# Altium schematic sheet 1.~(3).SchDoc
size 420 x 297 mm
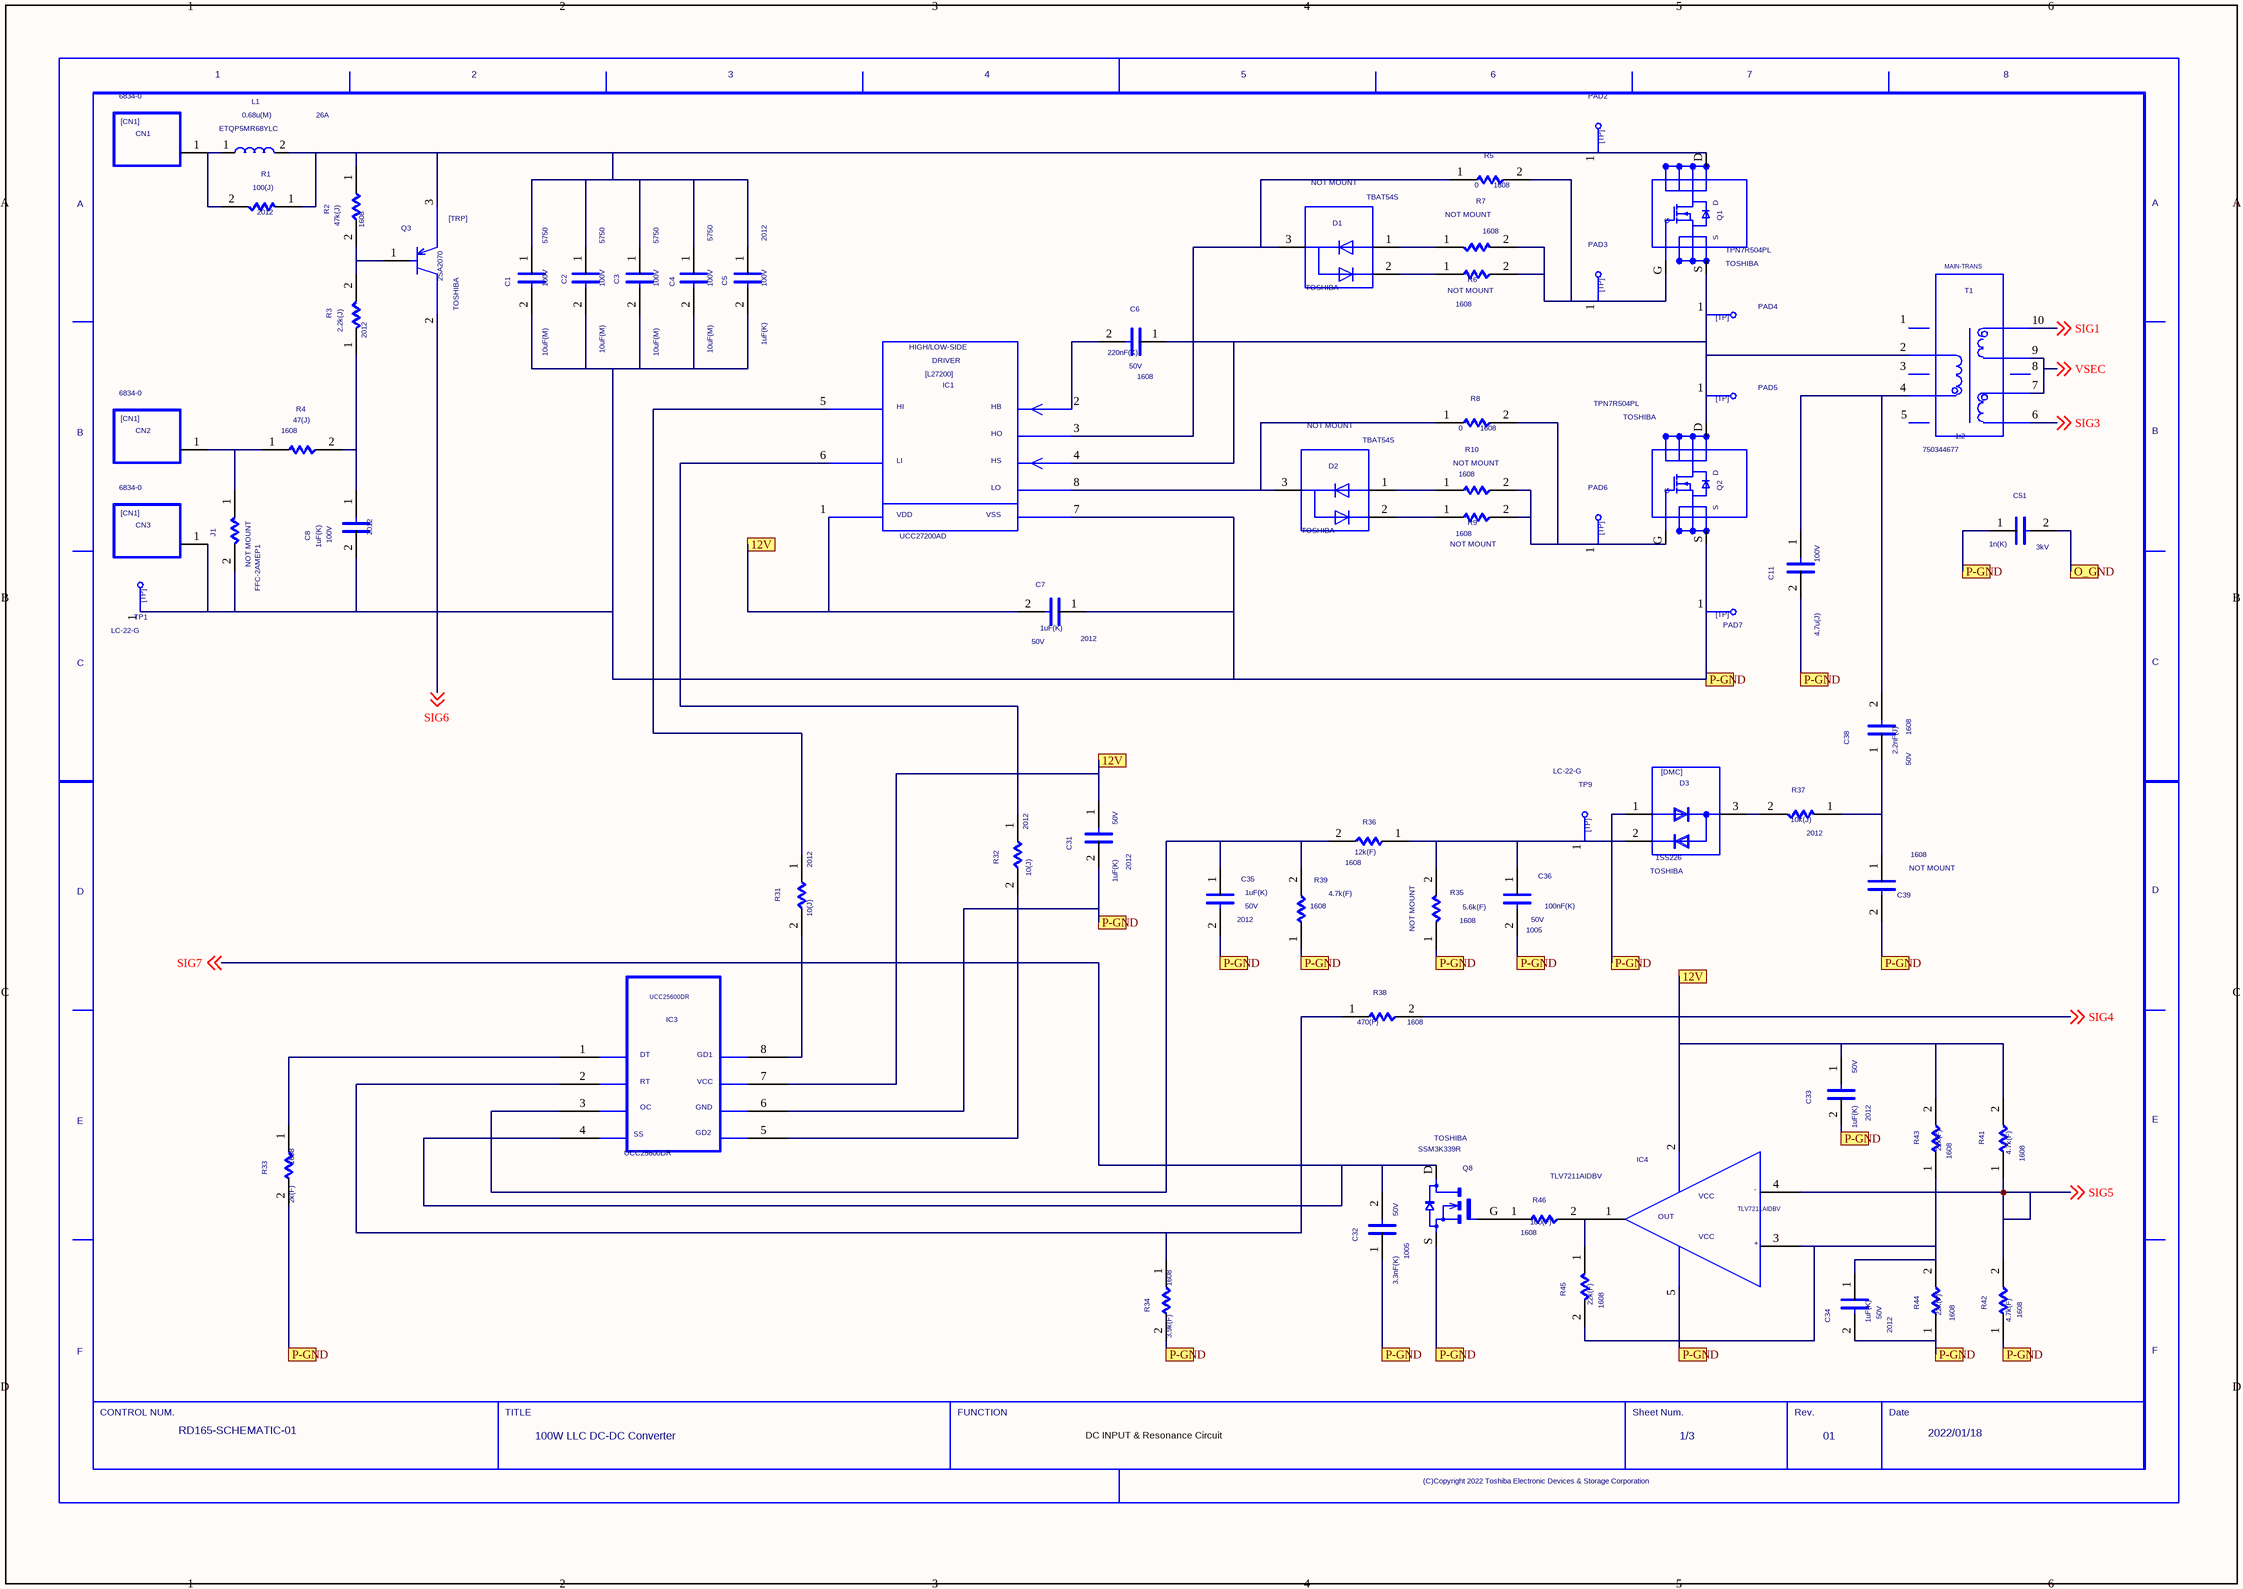
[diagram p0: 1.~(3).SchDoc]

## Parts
C1  SIZECODESMD: 5750  VAL2: 100V  VAL1: 10uF(M)  (hidden comment: C)
C2  SIZECODESMD: 5750  VAL2: 100V  VAL1: 10uF(M)  (hidden comment: C)
C3  SIZECODESMD: 5750  VAL2: 100V  VAL1: 10uF(M)  (hidden comment: C)
C4  SIZECODESMD: 5750  VAL2: 100V  VAL1: 10uF(M)  (hidden comment: C)
C5  SIZECODESMD: 2012  VAL2: 100V  VAL1: 1uF(K)  (hidden comment: C)
C6  SIZECODESMD: 1608  VAL2: 50V  VAL1: 220nF(K)  (hidden comment: C)
C7  SIZECODESMD: 2012  VAL2: 50V  VAL1: 1uF(K)  (hidden comment: C)
C8  SIZECODESMD: 2012  VAL2: 100V  VAL1: 1uF(K)  (hidden comment: C)
C11  VAL2: 100V  VAL1: 4.7u(J)  (hidden comment: C)
C31  SIZECODESMD: 2012  VAL2: 50V  VAL1: 1uF(K)  (hidden comment: C)
C32  SIZECODESMD: 1005  VAL2: 50V  VAL1: 3.3nF(K)  (hidden comment: C)
C33  SIZECODESMD: 2012  VAL2: 50V  VAL1: 1uF(K)  (hidden comment: C)
C34  SIZECODESMD: 2012  VAL2: 50V  VAL1: 1uF(K)  (hidden comment: C)
C35  SIZECODESMD: 2012  VAL2: 50V  VAL1: 1uF(K)  (hidden comment: C)
C36  SIZECODESMD: 1005  VAL2: 50V  VAL1: 100nF(K)  (hidden comment: C)
C38  SIZECODESMD: 1608  VAL2: 50V  VAL1: 2.2nF(J)  (hidden comment: C)
C39  NOTMOUNT: NOT MOUNT  SIZECODESMD: 1608  (hidden comment: C)
C51  VAL2: 3kV  VAL1: 1n(K)  (hidden comment: C)
CN1  VAL3: 6834-0  (hidden comment: CN1)
CN2  VAL3: 6834-0  (hidden comment: CN1)
CN3  VAL3: 6834-0  (hidden comment: CN1)
D1  USERCOMPTEXT3: TOSHIBA  NOTMOUNT: NOT MOUNT  (hidden comment: TBAT54S)
D2  USERCOMPTEXT3: TOSHIBA  NOTMOUNT: NOT MOUNT  (hidden comment: TBAT54S)
D3  USERCOMPTEXT3: TOSHIBA  VAL3: 1SS226  (hidden comment: DMC)
IC1  VAL3: UCC27200AD  (hidden comment: L27200)
IC3  UCC25600DR
IC4  TLV7211AIDBV
J1  VAL3: FFC-2AMEP1  NOTMOUNT: NOT MOUNT  (hidden comment: R)
L1  VAL3: ETQP5MR68YLC  VAL2: 26A  VAL1: 0.68u(M)  (hidden comment: L)
PAD2  TP  (value not drawn)
PAD3  TP  (value not drawn)
PAD4  TP  (value not drawn)
PAD5  TP  (value not drawn)
PAD6  TP  (value not drawn)
PAD7  TP  (value not drawn)
Q1  USERCOMPTEXT3: TOSHIBA  VAL3: TPN7R504PL  (hidden comment: TPN7B504PL)
Q2  USERCOMPTEXT3: TOSHIBA  VAL3: TPN7R504PL  (hidden comment: TPN7B504PL)
Q3  USERCOMPTEXT3: TOSHIBA  VAL3: 2SA2070  (hidden comment: TRP)
Q8  USERCOMPTEXT3: TOSHIBA  VAL3: SSM3K339R  (hidden comment: MFNF)
R1  SIZECODESMD: 2012  VAL1: 100(J)  (hidden comment: R)
R2  SIZECODESMD: 1608  VAL1: 47k(J)  (hidden comment: R)
R3  SIZECODESMD: 2012  VAL1: 2.2k(J)  (hidden comment: R)
R4  SIZECODESMD: 1608  VAL1: 47(J)  (hidden comment: R)
R5  SIZECODESMD: 1608  VAL1: 0  (hidden comment: R)
R6  NOTMOUNT: NOT MOUNT  SIZECODESMD: 1608  (hidden comment: R)
R7  NOTMOUNT: NOT MOUNT  SIZECODESMD: 1608  (hidden comment: R)
R8  SIZECODESMD: 1608  VAL1: 0  (hidden comment: R)
R9  NOTMOUNT: NOT MOUNT  SIZECODESMD: 1608  (hidden comment: R)
R10  NOTMOUNT: NOT MOUNT  SIZECODESMD: 1608  (hidden comment: R)
R31  SIZECODESMD: 2012  VAL1: 10(J)  (hidden comment: R)
R32  SIZECODESMD: 2012  VAL1: 10(J)  (hidden comment: R)
R33  SIZECODESMD: 1608  VAL1: 2k(F)  (hidden comment: R)
R34  SIZECODESMD: 1608  VAL1: 3.9k(F)  (hidden comment: R)
R35  NOTMOUNT: NOT MOUNT  SIZECODESMD: 1608  VAL1: 5.6k(F)  (hidden comment: R)
R36  SIZECODESMD: 1608  VAL1: 12k(F)  (hidden comment: R)
R37  SIZECODESMD: 2012  VAL1: 10k(J)  (hidden comment: R)
R38  SIZECODESMD: 1608  VAL1: 470(F)  (hidden comment: R)
R39  SIZECODESMD: 1608  VAL1: 4.7k(F)  (hidden comment: R)
R41  SIZECODESMD: 1608  VAL1: 4.7k(F)  (hidden comment: R)
R42  SIZECODESMD: 1608  VAL1: 4.7k(F)  (hidden comment: R)
R43  SIZECODESMD: 1608  VAL1: 22k(F)  (hidden comment: R)
R44  SIZECODESMD: 1608  VAL1: 22k(F)  (hidden comment: R)
R45  SIZECODESMD: 1608  VAL1: 22k(F)  (hidden comment: R)
R46  SIZECODESMD: 1608  VAL1: 100(F)  (hidden comment: R)
T1  VAL1: 1:2  VAL3: 750344677  (hidden comment: TRANS)
TP1  VAL3: LC-22-G  (hidden comment: TP)
TP9  VAL3: LC-22-G  (hidden comment: TP)
U?  DATE: 2022/01/18  TITLE: 100W LLC DC-DC Converter  REVISION: 01  SHEETNUMBER: 1/3  DRAWINGNUMBER: RD165-SCHEMATIC-01  (hidden comment: WAKU_DEF100)

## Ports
12V, O_GND, P-GND

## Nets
DN000002: IC3.2 R34.1 R38.1
DN000007: C11.1 C38.2 T1.4
DN000046: IC3.1 R33.1
N04422: C1.1 C2.1 C3.1 C4.1 C5.1 L1.2 PAD2.1 Q1.D Q3.3(E) R1.1 R2.1
N216469: Q3.1(B) R2.2 R3.2
N216829: C8.1 R3.1 R4.2
N216837: CN2.1 J1.1 R4.1
O_GND: C51.2 ; port O_GND
SIG1: T1.10 ; off-sheet SIG1
SIG3: T1.6 ; off-sheet SIG3
SIG4: R38.2 ; off-sheet SIG4
SIG5: IC4.4 R41.1 R42.2 ; off-sheet SIG5
SIG6: Q3.2(C) ; off-sheet SIG6
SIG7: C32.2 IC3.4 Q8.D ; off-sheet SIG7
SIG67: IC3.8 R31.2
SIG85: C34.1 IC4.3 R43.1 R44.2 R45.2
SIG102: C38.1 C39.1 R37.1
SIG104: C7.2 C31.1 C33.1 IC1.1 IC3.7 IC4.2 R41.2 R43.2 ; port 12V  [also labelled SIG130]
SIG119: CN1.1 L1.1 R1.2
SIG125: D2.3 IC1.8 R8.1
SIG126: IC1.6 R32.1
SIG127: IC1.5 R31.1
SIG128: D1.3 IC1.3 R5.1
SIG129: C6.2 IC1.2
SIG131: C6.1 IC1.4 PAD4.1 PAD5.1 Q1.S Q2.D T1.2
SIG190: IC3.5 R32.2
SIG212: D3.3(AC) R37.2
SIG218: PAD3.1 Q1.G R5.2 R6.2 R7.2
SIG231: PAD6.1 Q2.G R8.2 R9.2 R10.2
SIG233: C36.1 D3.2(C) R35.2 R36.1 TP9.1
SIG237: D2.1 R10.1
SIG239: D1.2 R6.1
SIG240: IC4.1 R45.1 R46.2
SIG248: D1.1 R7.1
SIG249: D2.2 R9.1
SIG267: C1.2 C2.2 C3.2 C4.2 C5.2 C7.1 C8.2 C11.2 C31.2 C32.1 C33.2 C34.2 C35.2 C36.2 C39.2 C51.1 CN3.1 D3.1(A) IC1.7 IC3.6 IC4.5 J1.2 PAD7.1 Q2.S Q8.S R33.2 R34.2 R35.1 R39.1 R42.1 R44.1 TP1.1 ; port P-GND  [also labelled SIG268]
SIG269: C35.1 IC3.3 R36.2 R39.2
SIG270: T1.7 T1.9 ; off-sheet VSEC  [also labelled VSEC]
NetQ8_G: Q8.G R46.1

Not connected (* = marked no-connect by the designer): T1 1 3 5 8

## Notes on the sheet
- DC INPUT & Resonance Circuit

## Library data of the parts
C1-C4 = C: OriginalSymbolOrigin: (2540,7620); RATEDVOLTAGE: 50; MAXGCOUNT: 1; TEMPCHARACTERI2: E; OUMEMAKER: KYC 京セラ; QUADMODEL: CON_10U; FNLEADFREETHET1GT2GMCTH1: N_N_N; OUMECLASSIFICATION: セラミックコンデンサ; CDBNAME: Chip5750_TD; NOMINALCAPACITA: 10u; OUMEMAKERKATAMEI: CX55Y5U106M50AT; CAPACITANCETOLE: M; CDMASTERCADCELG: DC848R; ADSMODELNAME: s_CX55Y5U106M50AT
C5 = C: OriginalSymbolOrigin: (2540,7620); RATEDVOLTAGE: 100; MAXGCOUNT: 1; OUMEMAKER: TDK ＴＤＫ; QUADMODEL: CON_1U; FNLEADFREETHET1GT2GMCTH1: 3_2_N; OUMECLASSIFICATION: セラミックコンデンサ; CDBNAME: Chip2012_GS_1; NOMINALCAPACITA: 1u; PMPRODUCTSTYPEG: HEV; OUMEMAKERKATAMEI: CGA4J3X7S2A105KT@@; CAPACITANCETOLE: K; CDMASTERCADCELG: KC0136; ADSMODELNAME: s_CGA4J3X7S2A105KT@@
C6 = C: OriginalSymbolOrigin: (2540,7620); RATEDVOLTAGE: 50; MAXGCOUNT: 1; OUMEMAKER: TDK ＴＤＫ; QUADMODEL: CON_220N; FNLEADFREETHET1GT2GMCTH1: N_N_N; OUMECLASSIFICATION: セラミックコンデンサ; CDBNAME: Chip1608_GS_1; NOMINALCAPACITA: 220n; PMPRODUCTSTYPEG: DA; OUMEMAKERKATAMEI: CGA3E3X7R1H224KT@@; CAPACITANCETOLE: K; CDMASTERCADCELG: KCK0238; ADSMODELNAME: s_CGA3E3X7R1H224KT@@
C7 C34 = C: OriginalSymbolOrigin: (2540,7620); RATEDVOLTAGE: 50; MAXGCOUNT: 1; OUMEMAKER: TDK ＴＤＫ; QUADMODEL: CON_1U; FNLEADFREETHET1GT2GMCTH1: 3_2_N; OUMECLASSIFICATION: セラミックコンデンサ; CDBNAME: Chip2012_GS_1; NOMINALCAPACITA: 1u; PMPRODUCTSTYPEG: DA; OUMEMAKERKATAMEI: CGA4J3X7R1H105KT@@; CAPACITANCETOLE: K; CDMASTERCADCELG: KC0159; ADSMODELNAME: s_CGA4J3X7R1H105KT@@
C8 C31 = C#1: OriginalSymbolOrigin: (2540,7620); CaptureCellPackProp: C##1; RATEDVOLTAGE: 50; MAXGCOUNT: 1; OUMEMAKER: TDK ＴＤＫ; QUADMODEL: CON_1U; FNLEADFREETHET1GT2GMCTH1: 3_2_N; OUMECLASSIFICATION: セラミックコンデンサ; CDBNAME: Chip2012_GS_1; NOMINALCAPACITA: 1u; PMPRODUCTSTYPEG: DA; OUMEMAKERKATAMEI: CGA4J3X7R1H105KT@@; CAPACITANCETOLE: K; CDMASTERCADCELG: KC0159; ADSMODELNAME: s_CGA4J3X7R1H105KT@@
C11 = C#1: OriginalSymbolOrigin: (2540,7620); CaptureCellPackProp: C##1; CDBNAME: CB182E0475***_AV
C32 = C: OriginalSymbolOrigin: (2540,7620); RATEDVOLTAGE: 50; MAXGCOUNT: 1; OUMEMAKER: TDK ＴＤＫ; QUADMODEL: CON_10N; FNLEADFREETHET1GT2GMCTH1: 3_0_N; OUMECLASSIFICATION: セラミックコンデンサ; CDBNAME: Chip1005_GS_2; NOMINALCAPACITA: 10n; PMPRODUCTSTYPEG: DA; OUMEMAKERKATAMEI: CGA2B3X7R1H103KT@@; CAPACITANCETOLE: K; CDMASTERCADCELG: KC0154; ADSMODELNAME: s_CGA2B3X7R1H103KT@@
C33 = C#1: OriginalSymbolOrigin: (2540,7620); CaptureCellPackProp: C##1; RATEDVOLTAGE: 50; MAXGCOUNT: 1; OUMEMAKER: TDK ＴＤＫ; QUADMODEL: CON_1U; FNLEADFREETHET1GT2GMCTH1: 3_2_N; OUMECLASSIFICATION: セラミックコンデンサ; CDBNAME: Chip2012_GS_1; NOMINALCAPACITA: 1u; PMPRODUCTSTYPEG: DA; OUMEMAKERKATAMEI: CGA4J3X7R1H105KTXXXS@@; CAPACITANCETOLE: K; CDMASTERCADCELG: KC0187; ADSMODELNAME: s_CGA4J3X7R1H105KTXXXS@@
C35 = C: OriginalSymbolOrigin: (2540,7620); CDBNAME: Chip2012_GS_1
C36 = C: OriginalSymbolOrigin: (2540,7620); CDBNAME: Chip1005_GS_2
C38 = C: OriginalSymbolOrigin: (2540,7620); RATEDVOLTAGE: 50; MAXGCOUNT: 1; OUMEMAKER: MRT 村田製作所; QUADMODEL: CON_2.2N; FNLEADFREETHET1GT2GMCTH1: 3_2_N; OUMECLASSIFICATION: セラミックコンデンサ; CDBNAME: Chip1608_GS_1; NOMINALCAPACITA: 2.2n; PMPRODUCTSTYPEG: HEV; OUMEMAKERKATAMEI: GCM1885C1H222JA16D@@; CAPACITANCETOLE: J; CDMASTERCADCELG: KC0134; ADSMODELNAME: s_GCM1885C1H222JA16D@@
C39 = C: OriginalSymbolOrigin: (2540,7620); RATEDVOLTAGE: 50; MAXGCOUNT: 1; OUMEMAKER: TDK ＴＤＫ; QUADMODEL: CON_10N; FNLEADFREETHET1GT2GMCTH1: 3_2_N; OUMECLASSIFICATION: セラミックコンデンサ; CDBNAME: Chip1608_GS_1; NOMINALCAPACITA: 10n; PMPRODUCTSTYPEG: HEV; OUMEMAKERKATAMEI: CGA3E2C0G1H103JT@@; VAL2: 50V; VAL1: 10nF(J); CAPACITANCETOLE: J; CDMASTERCADCELG: KC0134; ADSMODELNAME: s_CGA3E2C0G1H103JT@@
C51 = C: OriginalSymbolOrigin: (2540,7620); CDBNAME: Chip4632_AV
CN1-CN3 = CN1: OUMEPARTTYPE: CN; OriginalSymbolOrigin: (2540,12700); RATEDVOLTAGE: 0; MAXGCOUNT: 1; PLUGDIAMETER: 6m; OUMEMAKER: SMK エスエャPイ; FNLEADFREETHET1GT2GMCTH1: 9_1_N; OUMECLASSIFICATION: 単頭プラグ; CDBNAME: 6834-0-00-**-00-00-03-0_ML; OUMEMAKERKATAMEI: CMI1501-0101; CDMASTERCADCELG: CU0059
D1 D2 = TBAT54S: SAVEAREA0: -9930,-5308,32601,25918; TIME: 14:49:55; UPDATEUSER: t5459927; UPDATETIME: 18:16:07; SAVECOUNT: 5; OriginalSymbolOrigin: (5080,17780); CDBNAME: TBAT54S_TS
D3 = DMC: OUMEPARTTYPE: D; OriginalSymbolOrigin: (5080,20320); FORWARDVOLTAGEM: 0; MAXREVERSEVOLTA: 70; MAXGCOUNT: 1; OUMEMAKER: TSB 東芝; MOUNTINGFORMSMD: SMD; FNLEADFREETHET1GT2GMCTH1: 2_0_N; OUMECLASSIFICATION: 小信号ダイオード; CDBNAME: 1SS226_TS; PMPRODUCTSTYPEG: PC1; OUMEMAKERKATAMEI: 1SS226(TE85R); CDMASTERCADCELG: DD902A; ADSMODELNAME: s_1SS226_TE85R_
IC1 = L27200: OUMEPARTTYPE: IC; SAVEAREA0: -11719,-442,57445,43603; SAVECOUNT: 88; TIME: 14:04:55; UPDATEUSER: 19910145; UPDATETIME: 08:40:41; OriginalSymbolOrigin: (0,40640); MAXGCOUNT: 1; OUMEMAKER: TII テキサスインスツルメンツ; MOUNTINGFORMSMD: SMD; FNLEADFREETHET1GT2GMCTH1: N_N_N; OUMECLASSIFICATION: その他; CDBNAME: UCC272**AD_TI; OUMEMAKERKATAMEI: UCC27200D; CDMASTERCADCELG: I810D8; KIND: OTHER
IC3 = UCC25600DR: SAVEAREA0: -5309,-792,48736,38830; TIME: 17:00:15; UPDATEUSER: t5459927; UPDATETIME: 08:35:41; SAVECOUNT: 3; OriginalSymbolOrigin: (7620,35560); CDBNAME: UCC25600D*_TI
IC4 = TLV7211AIDBV: SAVECOUNT: 19; SAVEAREA0: -11523,-10867,52370,35975; TIME: 20:02:00; UPDATEUSER: t5459927; UPDATETIME: 08:40:37; OriginalSymbolOrigin: (7620,25400); CDBNAME: TLV7211AIDBVR_TI
J1 = R: OriginalSymbolOrigin: (5080,5080); CDBNAME: FFC-2AMEP1_HN
L1 = L: OriginalSymbolOrigin: (2540,5080); CDBNAME: ETQP5M***YLC_PN
PAD2-PAD7 = TP: TIME: 16:12:21; UPDATEUSER: fukuda-y; UPDATETIME: 16:18:11; SAVECOUNT: 2; SAVEAREA0: -242,-92,12810,7836; OriginalSymbolOrigin: (0,7620); CDBNAME: TP_I_TH0.5_LC1.1_RC1.2_GS
Q1 Q2 = TPN7B504PL: SAVEAREA0: -19342,-136,26697,27151; TIME: 18:57:44; UPDATEUSER: t5459927; UPDATETIME: 14:39:22; SAVECOUNT: 22; OriginalSymbolOrigin: (2540,20320); CDBNAME: TPN7R504PL_TS_A
Q3 = TRP: OUMEPARTTYPE: Q; TIME: 09:39:04; UPDATEUSER: 19870035; UPDATETIME: 15:34:42; SAVECOUNT: 12; SAVEAREA0: -5466,-244,29263,20886; OriginalSymbolOrigin: (5080,22860); MAXGCOUNT: 1; OUMEMAKER: TSB 東芝; MOUNTINGFORMSMD: SMD; FNLEADFREETHET1GT2GMCTH1: N_N_N; OUMECLASSIFICATION: PNPバイポーラトランジスタ; CDBNAME: 2SA2070_TS; PMPRODUCTSTYPEG: HD1; MAXGDVOLTAGE: 0; OUMEMAKERKATAMEI: 2SA2070(TE12L,F); CDMASTERCADCELG: DQ901D; ADSMODELNAME: s_2SA2070_TE12L_F_; MAXCOLLECTORCUR: -1
Q8 = MFNF: SAVECOUNT: 13; SAVEAREA0: -36202,-24391,51351,39797; TIME: 17:06:19; UPDATEUSER: t5459927; UPDATETIME: 17:07:36; OriginalSymbolOrigin: (5080,12700); CDBNAME: SSM3K339R_TS_A
R1 = R: OriginalSymbolOrigin: (5080,5080); MAXGCOUNT: 1; OUMEMAKER: NAE パナソニックエレクトロニックデバイス; QUADMODEL: RES_100; MOUNTINGFORMSMD: SMD; FNLEADFREETHET1GT2GMCTH1: 2_2_N; OUMECLASSIFICATION: 表面実装用固定抵抗器; CDBNAME: Chip2012_GS_1; RESISTANCETOLER: J; PMPRODUCTSTYPEG: PC1-PCS; POWERRATING: 250m; OUMEMAKERKATAMEI: ERJP06J101V; NOMINALRESISTAN: 100; VAL2: 400mW; CDMASTERCADCELG: KC0006; ADSMODELNAME: s_ERJP06J101V
R2 = R: OriginalSymbolOrigin: (5080,5080); MAXGCOUNT: 1; OUMEMAKER: NAE パナソニックエレクトロニックデバイス; QUADMODEL: RES_47K; MOUNTINGFORMSMD: SMD; FNLEADFREETHET1GT2GMCTH1: 3_2_N; OUMECLASSIFICATION: 表面実装用固定抵抗器; CDBNAME: Chip1608_GS_1; RESISTANCETOLER: J; PMPRODUCTSTYPEG: HEV; POWERRATING: 100m; OUMEMAKERKATAMEI: ERJ3GEYJ473V@@; NOMINALRESISTAN: 47K; VAL2: 100mW; CDMASTERCADCELG: KC0133; ADSMODELNAME: s_ERJ3GEYJ473V@@
R3 = R: OriginalSymbolOrigin: (5080,5080); MAXGCOUNT: 1; OUMEMAKER: KOA コーア; QUADMODEL: RES_2.2K; MOUNTINGFORMSMD: SMD; FNLEADFREETHET1GT2GMCTH1: 3_1_N; OUMECLASSIFICATION: 表面実装用固定抵抗器; CDBNAME: Chip2012_GS_1; RESISTANCETOLER: J; PMPRODUCTSTYPEG: HEV; POWERRATING: 250m; OUMEMAKERKATAMEI: SG73P2ATTD222J@@; NOMINALRESISTAN: 2.2K; VAL2: 400mW; CDMASTERCADCELG: KC0135; ADSMODELNAME: s_SG73P2ATTD222J@@
R4 = R: OriginalSymbolOrigin: (5080,5080); MAXGCOUNT: 1; OUMEMAKER: KOA コーア; QUADMODEL: RES_47; MOUNTINGFORMSMD: SMD; FNLEADFREETHET1GT2GMCTH1: 3_1_N; OUMECLASSIFICATION: 表面実装用固定抵抗器; CDBNAME: Chip1608_GS_1; RESISTANCETOLER: J; PMPRODUCTSTYPEG: HEV; POWERRATING: 100m; OUMEMAKERKATAMEI: RK73B1JTTD470J@@; NOMINALRESISTAN: 47; VAL2: 100mW; CDMASTERCADCELG: KC0133; ADSMODELNAME: s_RK73B1JTTD470J@@
R5 R8 = R: OriginalSymbolOrigin: (5080,5080); VAL2: 100mW; MAXGCOUNT: 1; OUMEMAKER: HDK 北陸電気工業; QUADMODEL: RES_0; MOUNTINGFORMSMD: SMD; FNLEADFREETHET1GT2GMCTH1: 2_1_N; OUMECLASSIFICATION: 表面実装用固定抵抗器; CDBNAME: Chip1608_GS_1; RESISTANCETOLER: X; PMPRODUCTSTYPEG: HD1; POWERRATING: 100m; OUMEMAKERKATAMEI: CR1/16 000V HSF; CDMASTERCADCELG: KC0167; ADSMODELNAME: s_CR1_16_000V_HSF
R6 R9 R10 = R: OriginalSymbolOrigin: (5080,5080); MAXGCOUNT: 1; OUMEMAKER: NAE パナソニックエレクトロニックデバイス; QUADMODEL: RES_10; MOUNTINGFORMSMD: SMD; FNLEADFREETHET1GT2GMCTH1: 3_1_N; OUMECLASSIFICATION: 表面実装用固定抵抗器; CDBNAME: Chip1608_GS_1; RESISTANCETOLER: F; POWERRATING: 63m; OUMEMAKERKATAMEI: ERJ3GEYF100V; NOMINALRESISTAN: 10; VAL2: 100mW; VAL1: 10(F); CDMASTERCADCELG: DR802R; ADSMODELNAME: s_ERJ3GEYF100V
R7 = R#1: OriginalSymbolOrigin: (5080,5080); CaptureCellPackProp: R##1; MAXGCOUNT: 1; OUMEMAKER: NAE パナソニックエレクトロニックデバイス; QUADMODEL: RES_10; MOUNTINGFORMSMD: SMD; FNLEADFREETHET1GT2GMCTH1: 3_1_N; OUMECLASSIFICATION: 表面実装用固定抵抗器; CDBNAME: Chip1608_GS_1; RESISTANCETOLER: F; POWERRATING: 63m; OUMEMAKERKATAMEI: ERJ3GEYF100V; NOMINALRESISTAN: 10; VAL2: 100mW; VAL1: 10(F); CDMASTERCADCELG: DR802R; ADSMODELNAME: s_ERJ3GEYF100V
R31 R32 = R: OriginalSymbolOrigin: (5080,5080); MAXGCOUNT: 1; OUMEMAKER: NAE パナソニックエレクトロニックデバイス; QUADMODEL: RES_10; MOUNTINGFORMSMD: SMD; FNLEADFREETHET1GT2GMCTH1: N_N_N; OUMECLASSIFICATION: 表面実装用固定抵抗器; CDBNAME: Chip2012_GS_1; RESISTANCETOLER: J; PMPRODUCTSTYPEG: SV1; POWERRATING: 125m; OUMEMAKERKATAMEI: (SV)ERJ6GEYJ100V; NOMINALRESISTAN: 10; VAL2: 400mW; CDMASTERCADCELG: KCK0273; ADSMODELNAME: s__SV_ERJ6GEYJ100V
R33 = R#1: OriginalSymbolOrigin: (5080,5080); CaptureCellPackProp: R##1; MAXGCOUNT: 1; OUMEMAKER: KOA コーア; QUADMODEL: RES_2K; MOUNTINGFORMSMD: SMD; FNLEADFREETHET1GT2GMCTH1: 3_1_N; OUMECLASSIFICATION: 表面実装用固定抵抗器; CDBNAME: Chip1608_GS_1; RESISTANCETOLER: F; PMPRODUCTSTYPEG: HEV; POWERRATING: 100m; OUMEMAKERKATAMEI: RK73H1JTTD2001F@@; NOMINALRESISTAN: 2K; VAL2: 100mW; CDMASTERCADCELG: KC0133; ADSMODELNAME: s_RK73H1JTTD2001F@@
R34 = R#1: OriginalSymbolOrigin: (5080,5080); CaptureCellPackProp: R##1; MAXGCOUNT: 1; OUMEMAKER: ROH ロー・; QUADMODEL: RES_3.9K; MOUNTINGFORMSMD: SMD; FNLEADFREETHET1GT2GMCTH1: 3_1_N; OUMECLASSIFICATION: 表面実装用固定抵抗器; CDBNAME: Chip1608_GS_1; RESISTANCETOLER: F; POWERRATING: 63m; OUMEMAKERKATAMEI: MCR03EZPFX3901; NOMINALRESISTAN: 3.9K; VAL2: 100mw; CDMASTERCADCELG: DR802R; ADSMODELNAME: s_MCR03EZPFX3901
R35 = R#1: OriginalSymbolOrigin: (5080,5080); CaptureCellPackProp: R##1; VAL2: 100mw; MAXGCOUNT: 1; OUMEMAKER: HDK 北陸電気工業; QUADMODEL: RES_7.5K; MOUNTINGFORMSMD: SMD; FNLEADFREETHET1GT2GMCTH1: 3_1_N; OUMECLASSIFICATION: 表面実装用固定抵抗器; CDBNAME: Chip1608_GS_1; RESISTANCETOLER: F; POWERRATING: 63m; OUMEMAKERKATAMEI: CR1/16 752FV; NOMINALRESISTAN: 7.5K; CDMASTERCADCELG: DR802R; ADSMODELNAME: s_CR1_16_752FV
R36 R39 = R: OriginalSymbolOrigin: (5080,5080); CDBNAME: Chip1608_GS_1
R37 = R: OriginalSymbolOrigin: (5080,5080); MAXGCOUNT: 1; OUMEMAKER: KOA コーア; QUADMODEL: RES_10K; MOUNTINGFORMSMD: SMD; FNLEADFREETHET1GT2GMCTH1: N_N_N; OUMECLASSIFICATION: 表面実装用固定抵抗器; CDBNAME: Chip2012_GS_1; RESISTANCETOLER: J; PMPRODUCTSTYPEG: DME; POWERRATING: 250m; OUMEMAKERKATAMEI: SG73S2ATTD103J; NOMINALRESISTAN: 10K; VAL2: 400mW; CDMASTERCADCELG: KC0006; ADSMODELNAME: s_SG73S2ATTD103J
R38 = R: OriginalSymbolOrigin: (5080,5080); MAXGCOUNT: 1; OUMEMAKER: KOA コーア; QUADMODEL: RES_470; MOUNTINGFORMSMD: SMD; FNLEADFREETHET1GT2GMCTH1: N_N_N; OUMECLASSIFICATION: 表面実装用固定抵抗器; CDBNAME: Chip1608_GS_1; RESISTANCETOLER: F; PMPRODUCTSTYPEG: DME; POWERRATING: 100m; OUMEMAKERKATAMEI: RK73H1JRTTD4700F; NOMINALRESISTAN: 470; VAL2: 100mW; CDMASTERCADCELG: KC0008; ADSMODELNAME: s_RK73H1JRTTD4700F
R41 R42 = R: OriginalSymbolOrigin: (5080,5080); MAXGCOUNT: 1; OUMEMAKER: NAE パナソニックエレクトロニックデバイス; QUADMODEL: RES_4.7K; MOUNTINGFORMSMD: SMD; FNLEADFREETHET1GT2GMCTH1: N_N_N; OUMECLASSIFICATION: 表面実装用固定抵抗器; CDBNAME: Chip1608_GS_1; RESISTANCETOLER: F; PMPRODUCTSTYPEG: DA; POWERRATING: 100m; OUMEMAKERKATAMEI: ERJ3EKF4701V@@; NOMINALRESISTAN: 4.7K; VAL2: 100mW; CDMASTERCADCELG: KCK0234; ADSMODELNAME: s_ERJ3EKF4701V@@
R43-R45 = R: OriginalSymbolOrigin: (5080,5080); MAXGCOUNT: 1; OUMEMAKER: NAE パナソニックエレクトロニックデバイス; QUADMODEL: RES_22K; MOUNTINGFORMSMD: SMD; FNLEADFREETHET1GT2GMCTH1: N_N_N; OUMECLASSIFICATION: 表面実装用固定抵抗器; CDBNAME: Chip1608_GS_1; RESISTANCETOLER: F; POWERRATING: 100m; OUMEMAKERKATAMEI: ERJ3EKF2202V; NOMINALRESISTAN: 22K; VAL2: 100mW; CDMASTERCADCELG: KC0008; ADSMODELNAME: s_ERJ3EKF2202V
R46 = R: OriginalSymbolOrigin: (5080,5080); MAXGCOUNT: 1; OUMEMAKER: KOA コーア; QUADMODEL: RES_100; MOUNTINGFORMSMD: SMD; FNLEADFREETHET1GT2GMCTH1: 3_1_N; OUMECLASSIFICATION: 表面実装用固定抵抗器; CDBNAME: Chip1608_GS_1; RESISTANCETOLER: F; POWERRATING: 63m; OUMEMAKERKATAMEI: RK73H1JTD1000F; NOMINALRESISTAN: 100; VAL2: 100mW; CDMASTERCADCELG: DR802R; ADSMODELNAME: s_RK73H1JTD1000F
T1 = TRANS: TIME: 11:13:20; UPDATEUSER: t5459927; UPDATETIME: 08:41:46; SAVECOUNT: 10; SAVEAREA0: -21734,-9489,47855,41529; OriginalSymbolOrigin: (-2540,33020); CDBNAME: PC40EER28_GS
TP1 TP9 = TP: TIME: 16:12:21; UPDATEUSER: fukuda-y; UPDATETIME: 16:18:11; SAVECOUNT: 2; SAVEAREA0: -242,-92,12810,7836; OriginalSymbolOrigin: (0,7620); CDBNAME: LC-22_GS
U? = WAKU_DEF100: PLOTTIME: HH:MM; SAVEAREA0: 198008,-65938,436964,90161; TIME: 14:30:25; UPDATEUSER: t5459927; UPDATETIME: 11:00:47; SAVECOUNT: 4; OriginalSymbolOrigin: (10160,284480)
